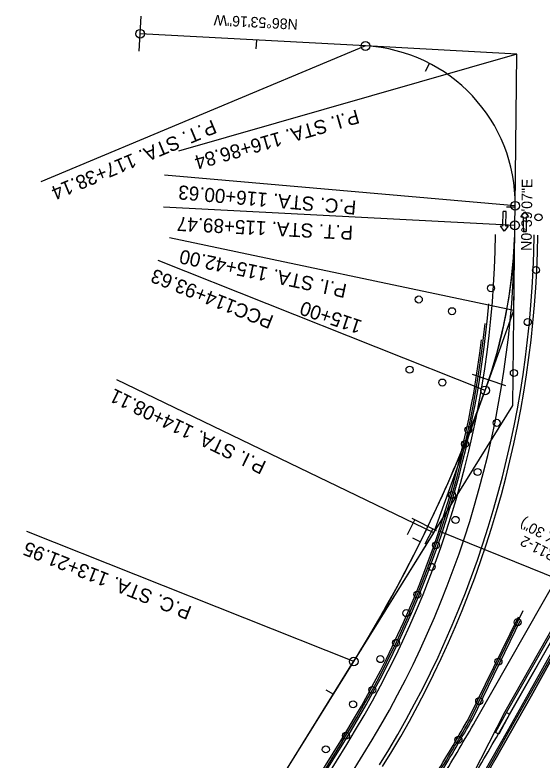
# Model space of a CAD drawing. Extents: x 659657 to 668193, y 633084 to 648639.
# Drawn here: x 662175.5 to 662475.1, y 643378.9 to 643802.8 of the extents above; entities that cross this region are included whole.
import ezdxf

# ---------------------------------------------------------------- set-up
doc = ezdxf.new("R2010")
doc.units = 0
for name, color, linetype in [('R_Draft', 7, 'Continuous'), ('R_MOT_Stage 1', 7, 'Continuous'), ('R_MOT_Stage 1_Striping', 7, 'Continuous'), ('R_MOT_Stage 2', 7, 'Continuous'), ('R_MOT_Stage 2_Striping', 7, 'Continuous'), ('R_MOT_Stage 3', 7, 'Continuous'), ('R_MOT_Stage 3_Striping', 7, 'Continuous'), ('R_MOT_Stage 3_Striping_PPM', 7, 'Continuous'), ('R_MOT_Stage 4', 7, 'Continuous'), ('R_MOT_Stage 4_Striping', 7, 'Continuous'), ('R_MOT_Stage 4_Striping_PPM', 7, 'Continuous'), ('R_MOT_Stage 5_Striping_PPM', 7, 'Continuous'), ('T_SIGNAL CONTROL CABINET', 7, 'Continuous')]:
    doc.layers.add(name, color=color, linetype=linetype)

msp = doc.modelspace()

# ---------------------------------------------------------------- linework, layer by layer
at = {"layer": 'R_Draft'}
for p, q in [((662402.91, 643515.68), (662398.42, 643507.02)), ((662401.18, 643516.58), (662414.9, 643509.47)), ((662413.03, 643510.44), (662408.54, 643501.78)), ((662416.93, 643509.09), (662522.12, 643466.36))]:
    msp.add_line(p, q, dxfattribs=at)
at = {"layer": 'R_MOT_Stage 1'}
for centre in [(662473.1, 643687.62), (662471.67, 643657.67), (662467.01, 643628.05), (662459.12, 643599.12), (662449.37, 643570.76), (662438.45, 643542.82), (662425.94, 643515.56), (662412.35, 643488.82), (662397.95, 643462.5), (662383.26, 643436.35), (662367.75, 643410.67), (662352.24, 643384.99)]:
    msp.add_circle(centre, 2, dxfattribs=at)
at = {"layer": 'R_MOT_Stage 1_Striping'}
for p, q in [((662374.73, 643785.14), (662246.72, 643792.1)), ((662460.82, 643780.46), (662374.73, 643785.14)), ((662459.84, 643694.25), (662460.82, 643780.46)), ((662459.71, 643683.09), (662459.84, 643694.25)), ((662458.54, 643580.63), (662459.71, 643683.09)), ((662459.16, 643634.72), (662459.71, 643683.09)), ((662442.76, 643589.21), (662459.16, 643634.72)), ((662413.55, 643508.16), (662442.76, 643589.21)), ((662368.1, 643434.97), (662458.54, 643580.63)), ((662368.1, 643434.97), (662413.55, 643508.16)), ((662175.55, 643124.86), (662368.1, 643434.97))]:
    msp.add_line(p, q, dxfattribs=at)
for points in [[(662246.18, 643782.11), (662247.27, 643802.08)], [(662246.18, 643782.11), (662247.27, 643802.08)], [(662312.68, 643783.5), (662312.95, 643788.5)], [(662374.73, 643785.14), (662190.24, 643707.9)], [(662460.82, 643780.46), (662268.59, 643725.25)], [(662408.95, 643770.74), (662411.25, 643775.18)], [(662459.84, 643694.25), (662260.6, 643711.66)], [(662459.71, 643683.09), (662259.97, 643693.38)], [(662454.83, 643693.68), (662459.83, 643693.62)], [(662459.16, 643634.72), (662263.45, 643675.94)], [(662442.76, 643589.21), (662256.94, 643663.17)], [(662435.37, 643598.41), (662454.33, 643592.05)], [(662413.55, 643508.16), (662233.53, 643595.3)], [(662368.1, 643434.97), (662182.26, 643508.88)], [(662401.57, 643505.36), (662406.05, 643503.14)], [(662352.27, 643418.96), (662356.52, 643416.32)]]:
    msp.add_lwpolyline(points, dxfattribs=at)
for centre in [(662246.72, 643792.1), (662374.73, 643785.14), (662459.84, 643694.25), (662459.71, 643683.09), (662442.76, 643589.21), (662368.1, 643434.97)]:
    msp.add_circle(centre, 2.5, dxfattribs=at)
for centre, radius, start, end in [((662369.84, 643695.27), 90, 359.348, 86.8876), ((662173.25, 643686.35), 286.48, 340.1804, 359.348), ((661672.73, 643866.74), 818.51, 328.16324, 340.18036)]:
    msp.add_arc(centre, radius, start, end, dxfattribs=at)
at = {"layer": 'R_MOT_Stage 2'}
for p, q in [((662183.21, 643104.02), (662360.74, 643389.94)), ((662184.91, 643102.96), (662362.44, 643388.89))]:
    msp.add_line(p, q, dxfattribs=at)
for centre in [(662446.11, 643647.35), (662405.08, 643640.92), (662423.94, 643634.27), (662399.82, 643601), (662418.43, 643593.68), (662433.19, 643566.73), (662431.41, 643558.73), (662423.89, 643529.69), (662414.82, 643501.1), (662404.23, 643473.03), (662392.16, 643445.58), (662378.63, 643418.81), (662363.68, 643392.8)]:
    msp.add_circle(centre, 2, dxfattribs=at)
for radius, start, end in [(585.96, 328.16324, 359.34796), (559.96, 328.1632, 355.3159), (557.96, 328.1632, 353.1704)]:
    msp.add_arc((661886.73, 643684.27), radius, start, end, dxfattribs=at)
at = {"layer": 'R_MOT_Stage 2_Striping'}
for p, q in [((662374.73, 643785.14), (662246.72, 643792.1)), ((662460.82, 643780.46), (662374.73, 643785.14)), ((662459.84, 643694.25), (662460.82, 643780.46)), ((662459.71, 643683.09), (662459.84, 643694.25)), ((662458.54, 643580.63), (662459.71, 643683.09)), ((662459.16, 643634.72), (662459.71, 643683.09)), ((662442.76, 643589.21), (662459.16, 643634.72)), ((662413.55, 643508.16), (662442.76, 643589.21)), ((662368.1, 643434.97), (662458.54, 643580.63)), ((662368.1, 643434.97), (662413.55, 643508.16)), ((662175.55, 643124.86), (662368.1, 643434.97)), ((662186.61, 643101.91), (662364.14, 643387.83)), ((662195.95, 643096.11), (662373.49, 643382.03))]:
    msp.add_line(p, q, dxfattribs=at)
for points in [[(662246.18, 643782.11), (662247.27, 643802.08)], [(662246.18, 643782.11), (662247.27, 643802.08)], [(662312.68, 643783.5), (662312.95, 643788.5)], [(662374.73, 643785.14), (662190.24, 643707.9)], [(662460.82, 643780.46), (662268.59, 643725.25)], [(662408.95, 643770.74), (662411.25, 643775.18)], [(662459.84, 643694.25), (662260.6, 643711.66)], [(662459.71, 643683.09), (662259.97, 643693.38)], [(662454.83, 643693.68), (662459.83, 643693.62)], [(662459.16, 643634.72), (662263.45, 643675.94)], [(662442.76, 643589.21), (662256.94, 643663.17)], [(662435.37, 643598.41), (662454.33, 643592.05)], [(662413.55, 643508.16), (662233.53, 643595.3)], [(662368.1, 643434.97), (662182.26, 643508.88)], [(662401.57, 643505.36), (662406.05, 643503.14)], [(662352.27, 643418.96), (662356.52, 643416.32)]]:
    msp.add_lwpolyline(points, dxfattribs=at)
for centre in [(662246.72, 643792.1), (662374.73, 643785.14), (662459.84, 643694.25), (662459.71, 643683.09), (662442.76, 643589.21), (662368.1, 643434.97)]:
    msp.add_circle(centre, 2.5, dxfattribs=at)
for centre, radius, start, end in [((662369.84, 643695.27), 90, 359.348, 86.8876), ((662173.25, 643686.35), 286.48, 340.1804, 359.348), ((661886.73, 643684.27), 561.96, 328.1632, 359.348), ((661886.73, 643684.27), 572.96, 328.16324, 359.34796), ((661886.73, 643684.27), 583.96, 328.16324, 359.34796), ((661672.73, 643866.74), 818.51, 328.16324, 340.18036)]:
    msp.add_arc(centre, radius, start, end, dxfattribs=at)
at = {"layer": 'R_MOT_Stage 3'}
for p, q in [((662480.76, 643436.42), (662468.89, 643415.34)), ((662468.89, 643415.34), (662457.01, 643394.26)), ((662457.01, 643394.26), (662448.32, 643378.9))]:
    msp.add_line(p, q, dxfattribs=at)
msp.add_lwpolyline([(662604.52, 643661.39), (662587.05, 643629.78), (662575.41, 643608.73), (662564.79, 643589.76), (662554.16, 643570.78), (662547.62, 643559.14), (662541.08, 643547.48), (662534.54, 643535.83), (662528, 643524.19), (662521.49, 643512.61), (662514.98, 643501.03), (662508.47, 643489.45), (662501.96, 643477.86), (662490.49, 643457.64), (662479.02, 643437.41), (662467.15, 643416.33), (662455.27, 643395.24), (662446.58, 643379.89), (662437.88, 643364.53)], dxfattribs=at)
at = {"layer": 'R_MOT_Stage 3_Striping'}
msp.add_lwpolyline([(662439.62, 643363.54), (662448.32, 643378.9), (662457.01, 643394.26), (662468.89, 643415.34), (662480.76, 643436.42), (662492.23, 643456.65), (662503.7, 643476.88), (662510.21, 643488.46), (662516.72, 643500.05), (662523.23, 643511.63), (662529.74, 643523.21), (662536.28, 643534.86), (662542.83, 643546.51), (662549.37, 643558.16), (662555.91, 643569.81), (662566.53, 643588.78), (662577.16, 643607.76), (662588.8, 643628.82), (662606.27, 643660.43)], dxfattribs=at)
at = {"layer": 'R_MOT_Stage 3_Striping_PPM'}
for p, q in [((662426.46, 643547.6), (662428.95, 643553.48)), ((662286.16, 643303), (662368.08, 643434.94))]:
    msp.add_line(p, q, dxfattribs=at)
for centre, radius, start, end in [((662173.25, 643686.35), 286.48, 340.1804, 358.2771), ((661672.73, 643866.74), 818.51, 337.49852, 340.18036), ((661672.71, 643866.7), 818.51, 328.16324, 337.05392)]:
    msp.add_arc(centre, radius, start, end, dxfattribs=at)
at = {"layer": 'R_MOT_Stage 4'}
for p, q in [((662454.93, 643406), (662629.22, 643712.99)), ((662456.67, 643405.01), (662630.96, 643712)), ((662433.76, 643403.13), (662461.66, 643460.48)), ((662435.53, 643402.2), (662463.1, 643458.86)), ((662454.93, 643406), (662456.67, 643405.01))]:
    msp.add_line(p, q, dxfattribs=at)
msp.add_lwpolyline([(662450.49, 643393.58), (662448.73, 643394.53), (662454.92, 643405.96), (662456.68, 643405.01)], close=True, dxfattribs=at)
for centre in [(662461.27, 643457.4), (662450.34, 643434.92), (662439.4, 643412.44), (662427.6, 643390.43)]:
    msp.add_circle(centre, 2, dxfattribs=at)
for radius, start, end in [(1134.42, 328.56301, 330.41188), (1136.42, 328.56153, 330.41509)]:
    msp.add_arc((661447.27, 643963.26), radius, start, end, dxfattribs=at)
at = {"layer": 'R_MOT_Stage 4_Striping'}
msp.add_lwpolyline([(662431.31, 643361.56), (662454.07, 643406.49), (662628.36, 643713.48)], dxfattribs=at)
at = {"layer": 'R_MOT_Stage 4_Striping_PPM'}
for p, q in [((662437.27, 643401.21), (662617.92, 643719.41)), ((662426.44, 643547.6), (662428.93, 643553.49)), ((662286.14, 643303.01), (662368.06, 643434.95))]:
    msp.add_line(p, q, dxfattribs=at)
for centre, radius, start, end in [((662173.23, 643686.35), 286.48, 340.1804, 358.2771), ((661672.71, 643866.74), 818.51, 337.49852, 340.18036), ((661672.69, 643866.71), 818.51, 328.16324, 337.05392), ((661447.27, 643963.26), 1138.42, 328.55574, 330.41509)]:
    msp.add_arc(centre, radius, start, end, dxfattribs=at)
at = {"layer": 'R_MOT_Stage 5_Striping_PPM'}
for p, q in [((662437.27, 643401.21), (662617.92, 643719.41)), ((662426.46, 643547.6), (662428.95, 643553.48)), ((662450.31, 643393.81), (662534.07, 643541.34)), ((662286.16, 643303), (662368.08, 643434.94))]:
    msp.add_line(p, q, dxfattribs=at)
for centre, radius, start, end in [((662173.27, 643686.34), 286.48, 340.1804, 358.2771), ((661672.75, 643866.73), 818.51, 337.49852, 340.18036), ((661672.71, 643866.7), 818.51, 328.16324, 337.05392), ((661447.27, 643963.26), 1138.42, 328.55574, 330.41509), ((661447.27, 643963.26), 1153.42, 328.55574, 330.41509)]:
    msp.add_arc(centre, radius, start, end, dxfattribs=at)
at = {"layer": 'T_SIGNAL CONTROL CABINET'}
for p, q in [((662452.86, 643682.72), (662452.95, 643691)), ((662452.86, 643682.72), (662452.95, 643691)), ((662454.64, 643690.98), (662452.95, 643691)), ((662454.64, 643690.98), (662452.95, 643691)), ((662454.55, 643682.7), (662454.64, 643690.98)), ((662454.55, 643682.7), (662454.64, 643690.98)), ((662463.01, 643687.96), (662465.3, 643690.86)), ((662463.01, 643687.96), (662465.3, 643690.86)), ((662465.3, 643690.86), (662467.51, 643687.91)), ((662465.3, 643690.86), (662467.51, 643687.91)), ((662463.01, 643687.96), (662464.42, 643687.95)), ((662463.01, 643687.96), (662464.42, 643687.95)), ((662464.42, 643687.95), (662464.33, 643679.67)), ((662464.42, 643687.95), (662464.33, 643679.67)), ((662466.11, 643687.93), (662466.01, 643679.65)), ((662466.11, 643687.93), (662466.01, 643679.65)), ((662466.11, 643687.93), (662467.51, 643687.91)), ((662466.11, 643687.93), (662467.51, 643687.91)), ((662452.86, 643682.72), (662451.45, 643682.74)), ((662453.67, 643679.79), (662451.45, 643682.74)), ((662452.86, 643682.72), (662451.45, 643682.74)), ((662453.67, 643679.79), (662451.45, 643682.74)), ((662455.95, 643682.69), (662453.67, 643679.79)), ((662455.95, 643682.69), (662453.67, 643679.79)), ((662455.95, 643682.69), (662454.55, 643682.7)), ((662455.95, 643682.69), (662454.55, 643682.7)), ((662464.33, 643679.67), (662466.01, 643679.65)), ((662464.33, 643679.67), (662466.01, 643679.65)), ((662434.66, 643402.69), (662464.44, 643463.91)), ((662361.59, 643389.42), (662184.06, 643103.49))]:
    msp.add_line(p, q, dxfattribs=at)
msp.add_lwpolyline([(662438.75, 643364.03), (662447.45, 643379.39), (662456.14, 643394.75), (662468.02, 643415.83), (662479.89, 643436.91), (662491.36, 643457.14), (662502.83, 643477.37), (662509.34, 643488.95), (662515.85, 643500.53), (662522.36, 643512.12), (662528.87, 643523.7), (662535.41, 643535.35), (662541.95, 643547), (662548.49, 643558.65), (662555.04, 643570.29), (662565.66, 643589.27), (662576.29, 643608.24), (662587.92, 643629.3), (662605.39, 643660.91)], dxfattribs=at)
for centre, radius, start, end in [((661886.73, 643684.27), 558.96, 328.1632, 354.1505), ((661447.27, 643963.26), 1135.42, 328.56301, 330.41188)]:
    msp.add_arc(centre, radius, start, end, dxfattribs=at)

# ---------------------------------------------------------------- texts
at = {"layer": 'R_Draft'}
for s, p in [('(48" X 30")', (662498.84, 643499.02)), ('(1) R11-2', (662494.93, 643491.15))]:
    msp.add_text(s, height=6, rotation=152.6108, dxfattribs=at).set_placement(p)
at = {"layer": 'R_MOT_Stage 1_Striping'}
for s, height, rotation, p in [('N86%%d53\'16"W', 6, 176.8876, (662336.45, 643800.32)), ('P.I. STA. 116+86.84', 8, 196.0227, (662369.83, 643749.13)), ('P.T. STA. 117+38.14', 8, 202.7175, (662287.9, 643743.37)), ('N0%%d39\'07"E', 6, 89.348, (662469.17, 643668.56)), ('P.C. STA. 116+00.63', 8, 175.0062, (662369.82, 643697.09)), ('P.T. STA. 115+89.47', 8, 177.0504, (662367.88, 643682.81)), ('P.I. STA. 115+42.00', 8, 168.1046, (662364.65, 643649.52)), ('PCC114+93.63', 8, 158.2964, (662323.19, 643631.42)), ('115+00', 8, 161.4548, (662373.41, 643628.72)), ('P.I. STA. 114+08.11', 8, 154.1718, (662318.98, 643548.38)), ('P.C. STA. 113+21.95', 8, 158.3118, (662276.61, 643465.98))]:
    msp.add_text(s, height=height, rotation=rotation, dxfattribs=at).set_placement(p)
at = {"layer": 'R_MOT_Stage 2_Striping'}
for s, height, rotation, p in [('N86%%d53\'16"W', 6, 176.8876, (662336.45, 643800.32)), ('P.I. STA. 116+86.84', 8, 196.0227, (662369.83, 643749.13)), ('P.T. STA. 117+38.14', 8, 202.7175, (662287.9, 643743.37)), ('N0%%d39\'07"E', 6, 89.348, (662469.17, 643668.56)), ('P.C. STA. 116+00.63', 8, 175.0062, (662369.82, 643697.09)), ('P.T. STA. 115+89.47', 8, 177.0504, (662367.88, 643682.81)), ('P.I. STA. 115+42.00', 8, 168.1046, (662364.65, 643649.52)), ('PCC114+93.63', 8, 158.2964, (662323.19, 643631.42)), ('115+00', 8, 161.4548, (662373.41, 643628.72)), ('P.I. STA. 114+08.11', 8, 154.1718, (662318.98, 643548.38)), ('P.C. STA. 113+21.95', 8, 158.3118, (662276.61, 643465.98))]:
    msp.add_text(s, height=height, rotation=rotation, dxfattribs=at).set_placement(p)

doc.saveas('drawing.dxf')
